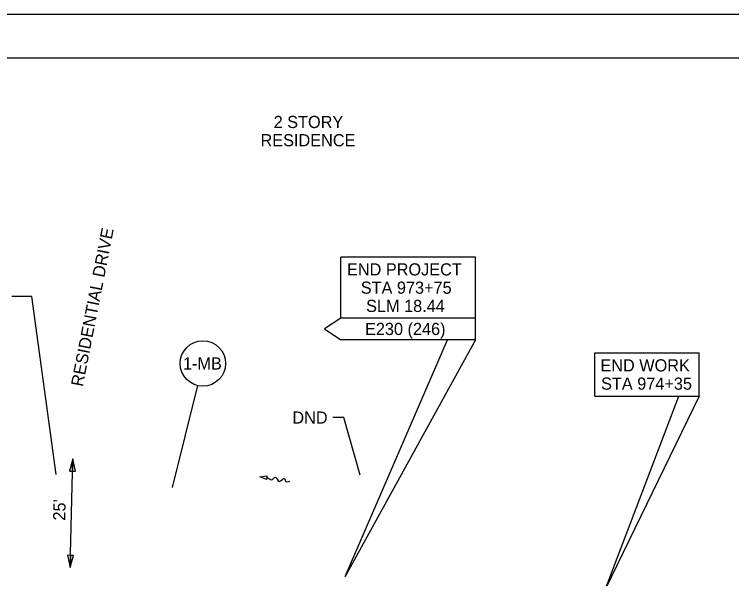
# Model space of a CAD drawing. Extents: x 1785 to 2465, y -264 to 295.
# Drawn here: x 2138.7 to 2303.8, y 46.4 to 176.2 of the extents above; entities that cross this region are included whole.
import ezdxf

# ---------------------------------------------------------------- set-up
doc = ezdxf.new("R2010")
doc.units = 0
for name, color, linetype in [('DR_P_Cells', 7, 'Continuous'), ('DR_P_Culvert', 7, 'Continuous'), ('PV_P_EOP', 7, 'Continuous'), ('RW_X_CL_100_Stations', 7, 'Continuous'), ('SV_X_Shot_Marker', 7, 'Continuous'), ('TX_P_1', 7, 'Continuous')]:
    doc.layers.add(name, color=color, linetype=linetype)

msp = doc.modelspace()

# ---------------------------------------------------------------- linework, layer by layer
at = {"layer": 'DR_P_Cells'}
for p, q in [((2152.15, 73.94), (2151.38, 71.16)), ((2152.08, 71.15), (2152.15, 73.94)), ((2152.15, 73.94), (2152.08, 71.15)), ((2152.78, 71.13), (2152.15, 73.94)), ((2151.38, 71.16), (2152.78, 71.13)), ((2151.38, 71.16), (2152.08, 71.15)), ((2152.08, 71.15), (2152.78, 71.13)), ((2152.28, 51.73), (2150.88, 51.77)), ((2150.88, 51.77), (2151.51, 48.95)), ((2151.58, 51.75), (2150.88, 51.77)), ((2151.58, 51.75), (2151.51, 48.95)), ((2151.51, 48.95), (2151.58, 51.75)), ((2151.51, 48.95), (2152.28, 51.73)), ((2152.28, 51.73), (2151.58, 51.75))]:
    msp.add_line(p, q, dxfattribs=at)
for points in [[(2152.78, 71.13), (2152.15, 73.94), (2151.38, 71.16)], [(2150.88, 51.77), (2151.51, 48.95), (2152.28, 51.73)]]:
    msp.add_lwpolyline(points, dxfattribs=at)
at = {"layer": 'DR_P_Culvert'}
msp.add_line((2180.8, 90.84), (2174.97, 67.35), dxfattribs=at)
at = {"layer": 'PV_P_EOP'}
for p, q in [((2195.16, 69.86), (2196.81, 70.03)), ((2196.68, 69.19), (2195.16, 69.86)), ((2196.81, 70.03), (2196.68, 69.19))]:
    msp.add_line(p, q, dxfattribs=at)
msp.add_spline([(2196.74, 69.61), (2196.8, 69.6), (2197.43, 69.35), (2197.82, 69.14), (2198.77, 69.74), (2199.6, 68.77), (2200.83, 69.42), (2200.99, 68.94), (2202.08, 68.79)], degree=3, dxfattribs=at)
at = {"layer": 'RW_X_CL_100_Stations'}
msp.add_lwpolyline([(1814.87, 166.23), (2454.87, 166.23), (2454.87, -253.77), (1814.87, -253.77)], close=True, dxfattribs=at)
at = {"layer": 'SV_X_Shot_Marker'}
msp.add_lwpolyline([(1784.87, -263.77), (2464.87, -263.77), (2464.87, 176.23), (1784.87, 176.23)], close=True, dxfattribs=at)
at = {"layer": 'TX_P_1'}
for p, q in [((2213.78, 106.35), (2213.78, 120.35)), ((2244.78, 120.35), (2213.78, 120.35)), ((2244.78, 101.35), (2244.78, 120.35)), ((2142.67, 111.28), (2138.06, 111.28)), ((2148.31, 70.36), (2142.67, 111.28)), ((2244.78, 106.35), (2213.78, 106.35)), ((2244.78, 101.35), (2213.78, 101.35)), ((2272.31, 88.37), (2272.31, 98.37)), ((2272.31, 98.37), (2296.31, 98.37)), ((2296.31, 88.37), (2296.31, 98.37)), ((2272.31, 88.37), (2296.31, 88.37)), ((2214.5, 83.46), (2211.98, 83.46)), ((2218.25, 70.21), (2214.5, 83.46)), ((2151.51, 48.95), (2152.15, 73.94))]:
    msp.add_line(p, q, dxfattribs=at)
for points in [[(2213.78, 106.35), (2210.09, 103.85), (2213.78, 101.35)], [(2244.78, 101.35), (2214.8, 46.89), (2238.36, 101.35)], [(2296.31, 88.37), (2274.73, 44.09), (2291.63, 88.37)]]:
    msp.add_lwpolyline(points, dxfattribs=at)
msp.add_circle((2182.06, 95.91), 5.22, dxfattribs=at)

# ---------------------------------------------------------------- texts
at = {"layer": 'DR_P_Culvert'}
for s, p in [('2 STORY', (2198.35, 150.07)), ('RESIDENCE', (2195.33, 145.87))]:
    msp.add_text(s, height=2.8, dxfattribs=at).set_placement(p)
msp.add_text('RESIDENTIAL DRIVE', height=2.8, rotation=78.8697, dxfattribs=at).set_placement((2154.42, 90.44))
at = {"layer": 'TX_P_1'}
for s, p in [('END PROJECT', (2215.23, 116.15)), ('STA 973+75', (2218.4, 111.95)), ('SLM 18.44', (2219.63, 107.75)), ('E230 (246)', (2219.38, 102.45)), ('1-MB', (2177.49, 94.51)), ('END WORK', (2273.55, 94.07)), ('STA 974+35', (2273.71, 89.87)), ('DND', (2202.66, 82.06))]:
    msp.add_text(s, height=2.8, dxfattribs=at).set_placement(p)
msp.add_text("25'", height=2.8, rotation=88.55, dxfattribs=at).set_placement((2150.37, 59.72))

doc.saveas('drawing.dxf')
